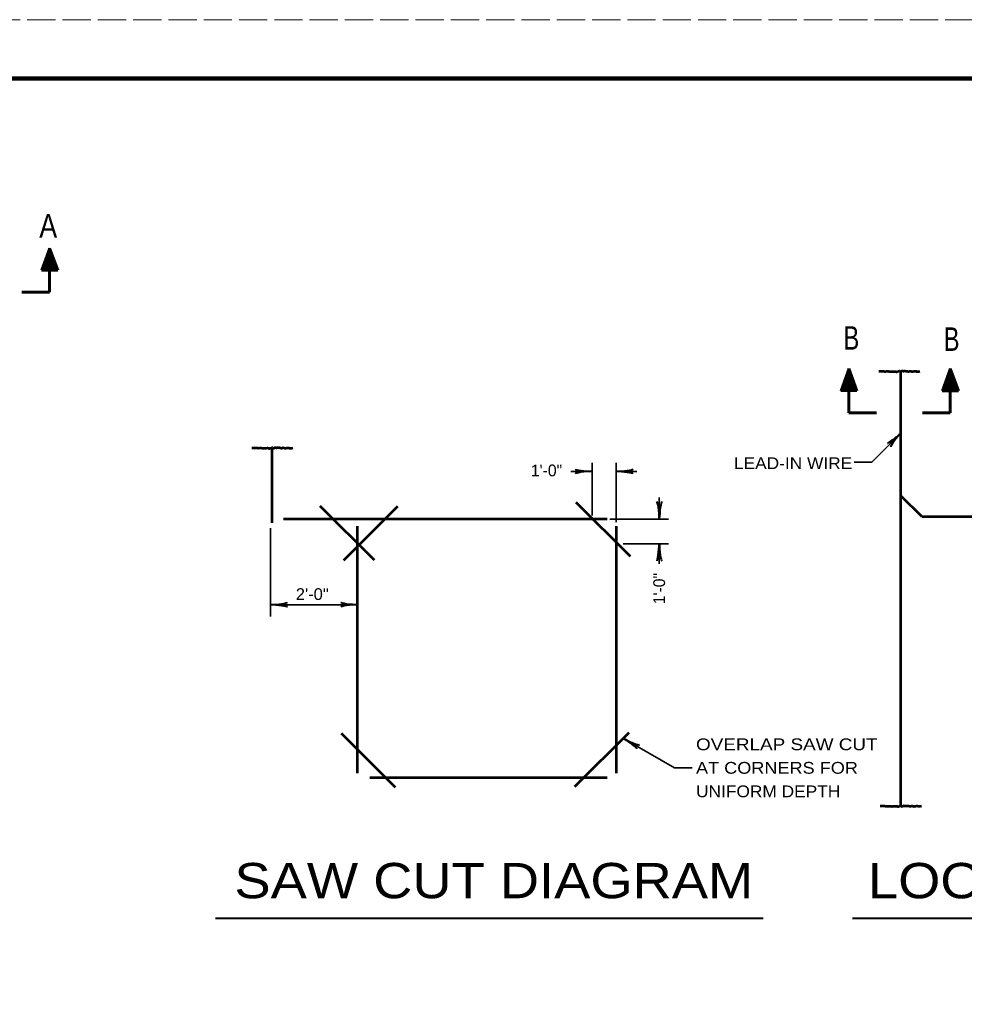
# Model space of a CAD drawing. Extents: x -58 to 622, y -372 to 68.
# Drawn here: x 216.3 to 376.8, y -99.4 to 68 of the extents above; entities that cross this region are included whole.
import ezdxf

# ---------------------------------------------------------------- set-up
doc = ezdxf.new("R2010")
doc.units = 0
doc.header["$LTSCALE"] = 0.8
doc.linetypes.add('LONG_DASHED', pattern=[7.5, 6, -1.5])
doc.layers.add('1', color=7, linetype='Continuous', lineweight=35)
doc.layers.add('61', color=7, linetype='Continuous', lineweight=35)

msp = doc.modelspace()

# ---------------------------------------------------------------- linework, layer by layer
at = {"layer": '1', "lineweight": 53}
for p, q in [((221.3807, 29.1601), (220.0126, 25.4013)), ((221.3807, 29.1601), (222.7488, 25.4013)), ((220.1598, 25.5852), (220.9852, 27.4662)), ((220.0126, 25.4013), (222.7488, 25.4013)), ((220.5821, 26.2378), (222.5974, 25.5661)), ((222.156, 26.1611), (220.8508, 26.1994)), ((357.1889, 8.6589), (355.8208, 4.9002)), ((357.1889, 8.6589), (358.557, 4.9002)), ((374.4443, 8.6589), (373.0762, 4.9002)), ((374.4443, 8.6589), (375.8123, 4.9002)), ((358.4097, 5.0841), (357.5844, 6.9651)), ((365.9924, 8.0001), (365.9924, -65.7447)), ((373.2234, 5.0841), (374.0487, 6.9651)), ((357.9875, 5.7367), (355.9722, 5.0649)), ((356.4136, 5.6599), (357.7188, 5.6982)), ((373.6457, 5.7367), (375.661, 5.0649)), ((375.2196, 5.6599), (373.9144, 5.6982)), ((358.557, 4.9002), (355.8208, 4.9002)), ((373.0762, 4.9002), (375.8123, 4.9002)), ((259.1281, -4.8118), (259.1281, -17.5567)), ((369.6012, -16.4908), (366.0657, -12.9553)), ((276.5712, -23.9092), (267.3787, -14.7167)), ((271.3582, -23.9091), (280.5507, -14.7167)), ((320.0787, -23.3077), (310.8862, -14.1152)), ((369.6012, -16.4908), (422.1311, -16.4908)), ((261.133, -16.8918), (316.133, -16.8918)), ((273.7271, -60.1245), (273.7271, -18.1245)), ((317.7271, -60.1245), (317.7271, -18.1245)), ((280.1801, -62.6047), (270.9877, -53.4123)), ((310.6553, -62.4042), (319.8477, -53.2118)), ((275.7692, -60.8918), (316.133, -60.8918))]:
    msp.add_line(p, q, dxfattribs=at)
at = {"layer": '1', "lineweight": 60}
for p, q in [((221.3807, 21.6601), (221.3807, 29.1601)), ((216.6665, 21.6601), (221.3807, 21.6601)), ((357.1889, 1.1589), (357.1889, 8.6589)), ((374.4443, 1.1589), (374.4443, 8.6589)), ((361.9031, 1.1589), (357.1889, 1.1589)), ((369.7301, 1.1589), (374.4443, 1.1589))]:
    msp.add_line(p, q, dxfattribs=at)
at = {"layer": '1'}
for p, q in [((313.5626, -16.3403), (313.5626, -7.3403)), ((317.6728, -17.4431), (317.6728, -7.3403)), ((309.9537, -8.8217), (313.5626, -8.8217)), ((317.6728, -8.8217), (321.1814, -8.8217)), ((324.9908, -13.2327), (324.9908, -16.8416)), ((316.57, -16.9418), (326.57, -16.9418)), ((258.9276, -18.4958), (258.9276, -33.4958)), ((318.8757, -21.1522), (326.57, -21.1522)), ((324.9908, -21.1522), (324.9908, -24.5607)), ((258.9276, -31.4898), (273.7271, -31.4898))]:
    msp.add_line(p, q, dxfattribs=at)
at = {"layer": '1', "lineweight": 40}
for p, q in [((249.5781, -84.8174), (342.6167, -84.8174)), ((357.8467, -84.8174), (443.6682, -84.8174))]:
    msp.add_line(p, q, dxfattribs=at)
at = {"layer": '1', "lineweight": 53}
for points in [[(221.1579, 28.3299), (221.5226, 28.5027), (221.1962, 28.4835), (221.465, 28.5795), (221.3114, 28.6371), (221.4458, 28.7138), (221.2922, 28.829), (220.1214, 25.5085), (221.3498, 28.7714), (220.179, 25.5468), (221.369, 28.6371), (220.3326, 25.6044), (221.1003, 27.9077), (220.1983, 25.6044), (221.4458, 28.8097), (222.6358, 25.4701), (221.4458, 28.6178), (222.5207, 25.662), (221.5417, 28.1188), (222.3287, 25.9307), (221.4266, 28.234), (222.1752, 26.1035), (221.8105, 26.0459), (222.2903, 25.854), (220.3902, 25.7964)], [(220.1022, 25.4701), (222.5974, 25.4701), (222.5782, 25.5661), (220.1598, 25.5468), (222.5014, 25.6237), (220.1598, 25.6428), (222.4631, 25.7004), (220.2366, 25.758), (222.4247, 25.8156), (220.3326, 25.7196), (222.5207, 25.7196), (222.3862, 25.9307), (220.275, 25.8732), (222.3671, 26.0075), (220.3709, 26.0075), (222.2519, 26.1418), (220.4093, 26.1227), (222.3287, 26.2187), (220.4861, 26.257), (222.2711, 26.3338), (220.4861, 26.3722), (222.2519, 26.4106), (220.5053, 26.4682), (222.1752, 26.5066), (220.5053, 26.5449), (222.156, 26.5642), (220.6397, 26.6025), (222.1368, 26.6601), (220.5821, 26.6601), (222.06, 26.7752), (220.6012, 26.7369), (222.0408, 26.852), (220.6012, 26.8137), (222.06, 26.9288), (220.6397, 26.9096), (222.06, 27.0247), (220.6781, 27.0056), (222.0024, 27.1016), (220.7164, 27.1207), (222.0024, 27.1783)], [(222.0024, 27.1783), (220.8124, 27.2359), (221.9257, 27.2935), (220.8124, 27.3511), (221.8488, 27.3702), (220.87, 27.4278), (221.8105, 27.447), (220.966, 27.5238), (221.8105, 27.5622), (220.8892, 27.6197), (221.7529, 27.6773), (220.9852, 27.7157), (221.7721, 27.7349), (220.966, 27.8309), (221.6569, 27.8309), (221.0427, 27.9269), (221.6953, 27.9269), (221.1003, 28.0037), (221.5993, 28.0804), (221.1195, 28.0804), (221.5802, 28.1572), (221.1962, 28.234), (221.5802, 28.2916), (221.1195, 28.1572)], [(220.4093, 25.9116), (220.7164, 25.9307), (220.8508, 26.1994)], [(357.4117, 7.8287), (357.047, 8.0015), (357.3733, 7.9823), (357.1046, 8.0783), (357.2582, 8.1359), (357.1237, 8.2127), (357.2773, 8.3278), (358.4482, 5.0073), (357.2197, 8.2702), (358.3906, 5.0457), (357.2006, 8.1359), (358.237, 5.1033), (357.4692, 7.4065), (358.3713, 5.1033), (357.1237, 8.3086), (355.9337, 4.9689), (357.1237, 8.1167), (356.0489, 5.1608), (357.0278, 7.6177), (356.2409, 5.4296), (357.143, 7.7328), (356.3944, 5.6023), (356.7591, 5.5447), (356.2792, 5.3528), (358.1794, 5.2953)], [(356.5672, 6.6772), (357.7572, 6.7348), (356.6439, 6.7923), (357.7572, 6.8499), (356.7208, 6.8691), (357.6996, 6.9267), (356.7591, 6.9458), (357.6036, 7.0227), (356.7591, 7.061), (357.6804, 7.1186), (356.8167, 7.1762), (357.5844, 7.2146), (356.7975, 7.2337), (357.6036, 7.3297), (356.9127, 7.3297), (357.5268, 7.4257), (356.8742, 7.4257), (357.4692, 7.5025), (356.9702, 7.5793), (357.4501, 7.5793), (356.9894, 7.656), (357.3733, 7.7328), (356.9894, 7.7904), (357.4501, 7.656)], [(374.2215, 7.8287), (374.5862, 8.0015), (374.2598, 7.9823), (374.5286, 8.0783), (374.375, 8.1359), (374.5094, 8.2127), (374.3558, 8.3278), (373.185, 5.0073), (374.4134, 8.2702), (373.2426, 5.0457), (374.4326, 8.1359), (373.3962, 5.1033), (374.1639, 7.4065), (373.2618, 5.1033), (374.5094, 8.3086), (375.6994, 4.9689), (374.5094, 8.1167), (375.5842, 5.1608), (374.6053, 7.6177), (375.3922, 5.4296), (374.4902, 7.7328), (375.2387, 5.6023), (374.8741, 5.5447), (375.3539, 5.3528), (373.4538, 5.2953)], [(375.066, 6.6772), (373.876, 6.7348), (374.9892, 6.7923), (373.876, 6.8499), (374.9124, 6.8691), (373.9336, 6.9267), (374.8741, 6.9458), (374.0296, 7.0227), (374.8741, 7.061), (373.9527, 7.1186), (374.8165, 7.1762), (374.0487, 7.2146), (374.8357, 7.2337), (374.0296, 7.3297), (374.7205, 7.3297), (374.1063, 7.4257), (374.7589, 7.4257), (374.1639, 7.5025), (374.6629, 7.5793), (374.1831, 7.5793), (374.6438, 7.656), (374.2598, 7.7328), (374.6438, 7.7904), (374.1831, 7.656)], [(358.4673, 4.9689), (355.9722, 4.9689), (355.9913, 5.0649), (358.4097, 5.0457), (356.0682, 5.1225), (358.4097, 5.1417), (356.1065, 5.1993), (358.333, 5.2568), (356.1449, 5.3144), (358.237, 5.2184), (356.0489, 5.2184), (356.1833, 5.4296), (358.2946, 5.372), (356.2025, 5.5063), (358.1987, 5.5063), (356.3177, 5.6407), (358.1602, 5.6215), (356.2409, 5.7175), (358.0835, 5.7558), (356.2985, 5.8327), (358.0835, 5.871), (356.3177, 5.9094), (358.0643, 5.967), (356.3944, 6.0054), (358.0643, 6.0438), (356.4136, 6.063), (357.9299, 6.1013), (356.4328, 6.1589), (357.9875, 6.1589), (356.5096, 6.2741), (357.9683, 6.2357), (356.5288, 6.3508), (357.9683, 6.3125), (356.5096, 6.4277), (357.9299, 6.4084), (356.5096, 6.5236), (357.8915, 6.5044), (356.5672, 6.6004), (357.8532, 6.6196), (356.5672, 6.6772)], [(358.1602, 5.4104), (357.8532, 5.4296), (357.7188, 5.6982)], [(373.1658, 4.9689), (375.661, 4.9689), (375.6418, 5.0649), (373.2234, 5.0457), (375.565, 5.1225), (373.2234, 5.1417), (375.5267, 5.1993), (373.3002, 5.2568), (375.4882, 5.3144), (373.3962, 5.2184), (375.5842, 5.2184), (375.4498, 5.4296), (373.3386, 5.372), (375.4307, 5.5063), (373.4345, 5.5063), (375.3155, 5.6407), (373.4729, 5.6215), (375.3922, 5.7175), (373.5497, 5.7558), (375.3347, 5.8327), (373.5497, 5.871), (375.3155, 5.9094), (373.5689, 5.967), (375.2387, 6.0054), (373.5689, 6.0438), (375.2196, 6.063), (373.7032, 6.1013), (375.2003, 6.1589), (373.6457, 6.1589), (375.1236, 6.2741), (373.6648, 6.2357), (375.1044, 6.3508), (373.6648, 6.3125), (375.1236, 6.4277), (373.7032, 6.4084), (375.1236, 6.5236), (373.7417, 6.5044), (375.066, 6.6004), (373.78, 6.6196), (375.066, 6.6772)], [(373.4729, 5.4104), (373.78, 5.4296), (373.9144, 5.6982)]]:
    msp.add_lwpolyline(points, dxfattribs=at)
at = {"layer": '1'}
for points in [[(358.1262, -7.2317), (361.1262, -7.2317), (366.0759, -2.2819)], [(318.901, -54.2206), (327.5612, -59.2206), (330.5612, -59.2206)]]:
    msp.add_lwpolyline(points, dxfattribs=at)
at = {"layer": '1', "lineweight": 40}
for centre, major_axis, ratio, start_param, end_param in [((365.134, -2.9246), (-1.3662, -1.1178), 0.07063, 6.28230741, 8.55970261), ((365.4997, -3.2489), (1.1523, 1.3731), 0.122415, 0.89635335, 3.14159265), ((312.4714, -9.098), (1.7857, 0.1562), 0.122415, 0.89635335, 3.14159265), ((312.4421, -8.6101), (1.7565, -0.1757), 0.07063, 3.14071475, 5.41810995), ((318.7933, -9.0334), (1.7565, -0.1757), 0.07063, 6.28230741, 8.55970261), ((318.7639, -8.5455), (-1.7857, -0.1562), 0.122415, 0.89635335, 3.14159265), ((324.7145, -15.7504), (0.1562, -1.7857), 0.122415, 0.89635335, 3.14159265), ((325.2024, -15.7211), (0.1757, 1.7565), 0.07063, 6.28230741, 8.55970261), ((324.7792, -22.2728), (-0.1757, -1.7565), 0.07063, 6.28230741, 8.55970261), ((325.2671, -22.2434), (-0.1562, 1.7857), 0.122415, 0.89635335, 3.14159265), ((260.0481, -31.7014), (1.7565, -0.1757), 0.07063, 6.28230741, 8.55970261), ((260.0188, -31.2135), (-1.7857, -0.1562), 0.122415, 0.89635335, 3.14159265), ((272.6359, -31.7661), (1.7857, 0.1562), 0.122415, 0.89635335, 3.14159265), ((272.6066, -31.2782), (1.7565, -0.1757), 0.07063, 3.14071475, 5.41810995), ((319.7656, -54.9641), (1.4333, -1.0303), 0.07063, 6.28230741, 8.55970261), ((319.9842, -54.5269), (-1.6245, 0.7576), 0.122415, 0.89635335, 3.14159265)]:
    msp.add_ellipse(centre, major_axis=major_axis, ratio=ratio, start_param=start_param, end_param=end_param, dxfattribs=at)
at = {"layer": '1', "lineweight": 53}
for points in [[(362.2842, 8.2205), (362.8356, 8.2332), (363.1614, 8.2082), (363.4371, 8.1832), (363.9133, 8.2082), (364.214, 8.1581), (364.4646, 8.1581), (364.7653, 8.1832), (365.1663, 8.1581), (365.3417, 8.1079), (365.4169, 8.133), (365.4922, 8.1581), (365.7929, 8.2583), (365.9182, 8.1832), (366.0937, 8.1581), (366.244, 8.2583), (366.3693, 8.2583), (366.4696, 8.2082), (366.6199, 8.2583), (366.8706, 8.2332), (367.1713, 8.2332), (367.2465, 8.1832), (367.4971, 8.2082), (367.7727, 8.2332), (367.848, 8.1832), (368.0986, 8.1581), (368.4494, 8.2332), (368.5497, 8.2332), (368.675, 8.1832), (368.9006, 8.1581), (369.2842, 8.2205)], [(255.7197, -4.8118), (256.2711, -4.7991), (256.5969, -4.8242), (256.8726, -4.8492), (257.3487, -4.8242), (257.6495, -4.8742), (257.9001, -4.8742), (258.2008, -4.8492), (258.6018, -4.8742), (258.7772, -4.9244), (258.8524, -4.8993), (258.9277, -4.8742), (259.2284, -4.774), (259.3537, -4.8492), (259.5292, -4.8742), (259.6795, -4.774), (259.8048, -4.774), (259.9051, -4.8242), (260.0554, -4.774), (260.3061, -4.7991), (260.6068, -4.7991), (260.682, -4.8492), (260.9326, -4.8242), (261.2082, -4.7991), (261.2835, -4.8492), (261.5341, -4.8742), (261.8849, -4.7991), (261.9852, -4.7991), (262.1105, -4.8492), (262.3361, -4.8742), (262.7197, -4.8118)], [(362.5348, -65.7129), (363.0863, -65.7002), (363.4121, -65.7253), (363.6877, -65.7502), (364.1639, -65.7253), (364.4647, -65.7753), (364.7152, -65.7753), (365.016, -65.7502), (365.417, -65.7753), (365.5924, -65.8255), (365.6676, -65.8004), (365.7428, -65.7753), (366.0436, -65.6751), (366.1688, -65.7502), (366.3443, -65.7753), (366.4947, -65.6751), (366.62, -65.6751), (366.7202, -65.7253), (366.8706, -65.6751), (367.1212, -65.7002), (367.422, -65.7002), (367.4972, -65.7502), (367.7477, -65.7253), (368.0234, -65.7002), (368.0987, -65.7502), (368.3492, -65.7753), (368.7001, -65.7002), (368.8003, -65.7002), (368.9257, -65.7502), (369.1513, -65.7753), (369.5348, -65.7129)]]:
    msp.add_spline(points, degree=3, dxfattribs=at)
at = {"layer": '61', "linetype": 'LONG_DASHED', "lineweight": 13}
msp.add_line((-58.4297, 67.9933), (621.5902, 67.9933), dxfattribs=at)
at = {"layer": '61', "lineweight": 158}
msp.add_lwpolyline([(610.6102, 57.9933), (-28.4297, 57.9933), (-28.4297, -362.0267)], dxfattribs=at)

# ---------------------------------------------------------------- texts
at = {"layer": '1'}
for s, height, width, p in [('A', 4, 0.85, (219.6241, 30.935)), ('B', 4, 0.75, (356.2929, 11.8712)), ('B', 4, 0.75, (373.3352, 11.6707)), ('LEAD-IN WIRE', 2, 1.1, (337.6757, -8.4322)), ('2\'-0"', 2, 1.05, (263.2133, -30.6878)), ('OVERLAP SAW CUT', 2, 1.2, (331.2315, -56.233)), ('AT CORNERS FOR', 2, 1.15, (331.2315, -60.233)), ('UNIFORM DEPTH', 2, 1.1, (331.2315, -64.233)), ('SAW CUT DIAGRAM', 6, 1.15, (252.786, -81.409)), ('LOOP WIRE PLAN', 6, 1.15, (360.4532, -81.409))]:
    msp.add_text(s, height=height, dxfattribs=dict(at, width=width)).set_placement(p)
msp.add_text('1\'-0"', height=2, dxfattribs=at).set_placement((303.162, -9.6607))
msp.add_text('1\'-0"', height=2, rotation=90, dxfattribs=at).set_placement((325.9684, -31.4145))

doc.saveas('drawing.dxf')
